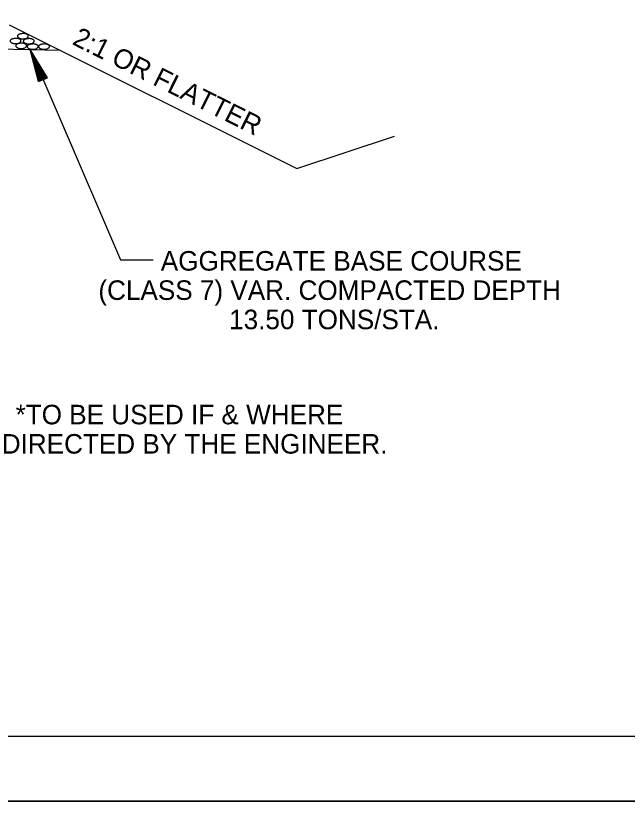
# Model space of a CAD drawing. Extents: x 2263886 to 2266026, y -3122850 to -3121850.
# Drawn here: x 2265245.9 to 2265264.71, y -3122443.82 to -3122419.69 of the extents above; entities that cross this region are included whole.
import ezdxf

# ---------------------------------------------------------------- set-up
doc = ezdxf.new("R2010")
doc.units = 0
for name, color, linetype in [('_CIVIL_CONSTRUCTION', 7, 'Continuous'), ('R_Border Notes', 7, 'Continuous'), ('R_Border Prem', 7, 'Continuous'), ('R_Draft', 7, 'Continuous')]:
    doc.layers.add(name, color=color, linetype=linetype)

msp = doc.modelspace()

# ---------------------------------------------------------------- linework, layer by layer
at = {"layer": '_CIVIL_CONSTRUCTION'}
msp.add_line((2265192.355, -3122443.817), (2265359.022, -3122443.817), dxfattribs=at)
for points in [[(2265192.352, -3122337.151), (2265359.022, -3122337.151), (2265359.022, -3122443.82), (2265192.352, -3122443.82)], [(2265315.516, -3122339.098), (2265315.516, -3122344.038), (2265333.382, -3122344.038), (2265333.382, -3122345.498), (2265344.981, -3122345.498), (2265344.981, -3122357.664), (2265356.646, -3122357.664), (2265356.646, -3122441.828), (2265198.556, -3122441.828), (2265198.556, -3122339.098)]]:
    msp.add_lwpolyline(points, close=True, dxfattribs=at)
at = {"layer": 'R_Border Notes'}
for p, q in [((2265245.709, -3122419.966), (2265254.552, -3122424.387)), ((2265243.706, -3122420.679), (2265247.279, -3122420.75)), ((2265254.552, -3122424.387), (2265257.552, -3122423.387))]:
    msp.add_line(p, q, dxfattribs=at)
at = {"layer": 'R_Border Prem'}
for p, q in [((2265246.354, -3122420.732), (2265247.271, -3122422.865)), ((2265246.604, -3122421.712), (2265246.354, -3122420.732)), ((2265246.881, -3122421.595), (2265246.354, -3122420.732)), ((2265246.627, -3122421.702), (2265246.419, -3122420.886)), ((2265246.858, -3122421.605), (2265246.419, -3122420.886)), ((2265246.834, -3122421.615), (2265246.486, -3122421.044)), ((2265246.651, -3122421.692), (2265246.486, -3122421.044)), ((2265246.674, -3122421.682), (2265246.55, -3122421.198)), ((2265246.811, -3122421.625), (2265246.55, -3122421.198)), ((2265246.788, -3122421.634), (2265246.616, -3122421.354)), ((2265246.698, -3122421.672), (2265246.616, -3122421.354)), ((2265246.604, -3122421.712), (2265246.881, -3122421.595)), ((2265246.764, -3122421.644), (2265246.681, -3122421.508)), ((2265246.721, -3122421.663), (2265246.681, -3122421.508)), ((2265247.271, -3122422.865), (2265249.128, -3122427.183)), ((2265247.387, -3122423.135), (2265247.681, -3122423.818)), ((2265249.128, -3122427.183), (2265250.128, -3122427.183))]:
    msp.add_line(p, q, dxfattribs=at)
for points in [[(2265245.747, -3122420.434), (2265245.74, -3122420.445), (2265245.737, -3122420.455), (2265245.734, -3122420.468), (2265245.736, -3122420.476), (2265245.742, -3122420.489), (2265245.75, -3122420.499), (2265245.764, -3122420.51), (2265245.773, -3122420.518), (2265245.781, -3122420.521), (2265245.798, -3122420.53), (2265245.828, -3122420.539), (2265245.873, -3122420.547), (2265245.919, -3122420.547), (2265245.968, -3122420.54), (2265246.017, -3122420.524), (2265246.045, -3122420.505), (2265246.063, -3122420.485), (2265246.067, -3122420.468), (2265246.067, -3122420.453), (2265246.062, -3122420.437), (2265246.056, -3122420.429), (2265246.047, -3122420.421), (2265246.035, -3122420.414), (2265246.021, -3122420.405), (2265246.01, -3122420.401), (2265245.988, -3122420.393), (2265245.957, -3122420.388), (2265245.914, -3122420.386), (2265245.883, -3122420.388), (2265245.851, -3122420.391), (2265245.834, -3122420.395), (2265245.811, -3122420.4), (2265245.785, -3122420.409), (2265245.77, -3122420.417), (2265245.752, -3122420.43), (2265245.744, -3122420.437)], [(2265245.972, -3122420.286), (2265245.965, -3122420.297), (2265245.962, -3122420.307), (2265245.959, -3122420.32), (2265245.961, -3122420.328), (2265245.967, -3122420.341), (2265245.975, -3122420.351), (2265245.989, -3122420.362), (2265245.998, -3122420.37), (2265246.006, -3122420.373), (2265246.023, -3122420.382), (2265246.053, -3122420.391), (2265246.098, -3122420.399), (2265246.144, -3122420.399), (2265246.193, -3122420.392), (2265246.242, -3122420.376), (2265246.27, -3122420.357), (2265246.288, -3122420.337), (2265246.292, -3122420.32), (2265246.292, -3122420.305), (2265246.287, -3122420.289), (2265246.281, -3122420.281), (2265246.272, -3122420.273), (2265246.26, -3122420.266), (2265246.246, -3122420.257), (2265246.235, -3122420.253), (2265246.213, -3122420.245), (2265246.182, -3122420.24), (2265246.139, -3122420.238), (2265246.108, -3122420.24), (2265246.076, -3122420.243), (2265246.059, -3122420.247), (2265246.036, -3122420.252), (2265246.01, -3122420.261), (2265245.995, -3122420.269), (2265245.977, -3122420.282), (2265245.969, -3122420.289)], [(2265246.151, -3122420.441), (2265246.144, -3122420.452), (2265246.141, -3122420.462), (2265246.138, -3122420.475), (2265246.14, -3122420.483), (2265246.146, -3122420.496), (2265246.154, -3122420.506), (2265246.168, -3122420.517), (2265246.177, -3122420.525), (2265246.185, -3122420.528), (2265246.202, -3122420.537), (2265246.232, -3122420.546), (2265246.277, -3122420.554), (2265246.323, -3122420.554), (2265246.372, -3122420.547), (2265246.421, -3122420.531), (2265246.449, -3122420.512), (2265246.467, -3122420.492), (2265246.471, -3122420.475), (2265246.471, -3122420.46), (2265246.466, -3122420.444), (2265246.46, -3122420.436), (2265246.451, -3122420.428), (2265246.439, -3122420.421), (2265246.425, -3122420.412), (2265246.414, -3122420.408), (2265246.392, -3122420.4), (2265246.361, -3122420.395), (2265246.318, -3122420.393), (2265246.287, -3122420.395), (2265246.255, -3122420.398), (2265246.238, -3122420.402), (2265246.215, -3122420.407), (2265246.189, -3122420.416), (2265246.174, -3122420.424), (2265246.156, -3122420.437), (2265246.148, -3122420.444)], [(2265245.919, -3122420.582), (2265245.912, -3122420.593), (2265245.909, -3122420.603), (2265245.906, -3122420.616), (2265245.908, -3122420.624), (2265245.914, -3122420.637), (2265245.922, -3122420.647), (2265245.936, -3122420.658), (2265245.945, -3122420.666), (2265245.953, -3122420.669), (2265245.97, -3122420.678), (2265246, -3122420.687), (2265246.045, -3122420.695), (2265246.091, -3122420.695), (2265246.14, -3122420.688), (2265246.189, -3122420.672), (2265246.217, -3122420.653), (2265246.235, -3122420.633), (2265246.239, -3122420.616), (2265246.239, -3122420.601), (2265246.234, -3122420.585), (2265246.228, -3122420.577), (2265246.219, -3122420.569), (2265246.207, -3122420.562), (2265246.193, -3122420.553), (2265246.182, -3122420.549), (2265246.16, -3122420.541), (2265246.129, -3122420.536), (2265246.086, -3122420.534), (2265246.055, -3122420.536), (2265246.023, -3122420.539), (2265246.006, -3122420.543), (2265245.983, -3122420.548), (2265245.957, -3122420.557), (2265245.942, -3122420.565), (2265245.924, -3122420.578), (2265245.916, -3122420.585)], [(2265246.273, -3122420.606), (2265246.266, -3122420.617), (2265246.263, -3122420.627), (2265246.26, -3122420.64), (2265246.262, -3122420.648), (2265246.268, -3122420.661), (2265246.276, -3122420.671), (2265246.29, -3122420.682), (2265246.299, -3122420.69), (2265246.307, -3122420.693), (2265246.324, -3122420.702), (2265246.354, -3122420.711), (2265246.399, -3122420.719), (2265246.445, -3122420.719), (2265246.494, -3122420.712), (2265246.543, -3122420.696), (2265246.571, -3122420.677), (2265246.589, -3122420.657), (2265246.593, -3122420.64), (2265246.593, -3122420.625), (2265246.588, -3122420.609), (2265246.582, -3122420.601), (2265246.573, -3122420.593), (2265246.561, -3122420.586), (2265246.547, -3122420.577), (2265246.536, -3122420.573), (2265246.514, -3122420.565), (2265246.483, -3122420.56), (2265246.44, -3122420.558), (2265246.409, -3122420.56), (2265246.377, -3122420.563), (2265246.36, -3122420.567), (2265246.337, -3122420.572), (2265246.311, -3122420.581), (2265246.296, -3122420.589), (2265246.278, -3122420.602), (2265246.27, -3122420.609)], [(2265246.621, -3122420.606), (2265246.614, -3122420.617), (2265246.611, -3122420.627), (2265246.608, -3122420.64), (2265246.61, -3122420.648), (2265246.616, -3122420.661), (2265246.624, -3122420.671), (2265246.638, -3122420.682), (2265246.647, -3122420.69), (2265246.655, -3122420.693), (2265246.672, -3122420.702), (2265246.702, -3122420.711), (2265246.747, -3122420.719), (2265246.793, -3122420.719), (2265246.842, -3122420.712), (2265246.891, -3122420.696), (2265246.919, -3122420.677), (2265246.937, -3122420.657), (2265246.941, -3122420.64), (2265246.941, -3122420.625), (2265246.936, -3122420.609), (2265246.93, -3122420.601), (2265246.921, -3122420.593), (2265246.909, -3122420.586), (2265246.895, -3122420.577), (2265246.884, -3122420.573), (2265246.862, -3122420.565), (2265246.831, -3122420.56), (2265246.788, -3122420.558), (2265246.757, -3122420.56), (2265246.725, -3122420.563), (2265246.708, -3122420.567), (2265246.685, -3122420.572), (2265246.659, -3122420.581), (2265246.644, -3122420.589), (2265246.626, -3122420.602), (2265246.618, -3122420.609)]]:
    msp.add_spline(points, degree=3, dxfattribs=at)
at = {"layer": 'R_Draft'}
msp.add_line((2265356.646, -3122441.828), (2265198.556, -3122441.828), dxfattribs=at)

# ---------------------------------------------------------------- texts
at = {"layer": 'R_Border Prem'}
msp.add_text('2:1 OR FLATTER', height=0.6, rotation=333.435, dxfattribs=at).set_placement((2265247.612, -3122420.554))
for s, p in [('AGGREGATE BASE COURSE', (2265250.366, -3122427.519)), ('(CLASS 7) VAR. COMPACTED DEPTH', (2265248.448, -3122428.419)), ('13.50 TONS/STA.', (2265252.468, -3122429.319)), ('*TO BE USED IF & WHERE', (2265245.902, -3122432.24)), ('DIRECTED BY THE ENGINEER.', (2265245.476, -3122433.14))]:
    msp.add_text(s, height=0.6, dxfattribs=at).set_placement(p)

doc.saveas('drawing.dxf')
